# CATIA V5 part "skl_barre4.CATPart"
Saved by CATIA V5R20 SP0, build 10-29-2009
Part number: skl_barre4
Publications: "Barre_4", "Axe_Pivot_b4b2", "Axe_Pivot_b4b5"
Bounding box of the stored display mesh (mm): x -159.748 to 234.923, y 0 to 201.792, z 0 to 20
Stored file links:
  C:\Users\Matthieu\Desktop\IFMA\Cours 2A\Thinkmotion\skl_barre4.CATPart
  C:\Users\Matthieu\Desktop\IFMA\Cours 2A\Thinkmotion\skl_IAO_bis.CATProduct
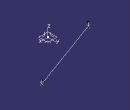
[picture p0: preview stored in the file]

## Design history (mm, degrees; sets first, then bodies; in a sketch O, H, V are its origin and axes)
AxisSystem1: origin (0, 0, 0), X (1, 0, 0), Y (0, 1, 0), Z (0, 0, 1)
Set1
  Point1 "Point.C": linked copy from another document
  Point2 "Point.E": linked copy from another document
  Plane1 "Plan_Ref": linked copy from another document
Body1 (main body)
  Line1 "Barre_4": type PtPt, FirstPoint Point1, SecondPoint Point2
  Line2 "Axe_Pivot_b4b2": type Normal, RefPoint Point1, RefSkin Plane1, Start 0, End 20
  Line3 "Axe_Pivot_b4b5": type Normal, RefPoint Point2, RefSkin Plane1, Start 0, End 20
